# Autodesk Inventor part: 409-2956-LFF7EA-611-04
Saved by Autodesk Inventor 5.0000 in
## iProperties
Created: 2010-06
Part Number: 409-2956-LFF7EA-611-04
Cost Center: 0 lbmass
Material: A36 STEEL PLATE
Document SubType Name: Sheet Metal
Designer: S. Boerckel
Authority: 0 in^3
Mass: 83463.9 g
Surface Area: 17206.4 cm^2
Volume: 10618.8 cm^3
Density: 7.86 g/cm^3
Flat Pattern Width: 68.58 cm
Flat Pattern Length: 121.92 cm
Flat Pattern Area: 8361.27 cm^2
Sheet Metal Rule: 1/2"Thk
Sheet Metal Width: 16.0000 in
Sheet Metal Length: 80.0000 in^2
Description: PUMP FOOT PLATE
User Status: BURN
SaveDate: 2008-01-15
SaveTime: 10:24
FileName: Sheet Metal
Wide: =<Flat Pattern Width>cm
Length: =<Flat Pattern Length>cm
Thickness: 0.5000 in
SMR: =<Sheet Metal Rule> - <Material>
Author: S. Boerckel
Revision Number: 0
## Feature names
1. Hole1
2. Plate1
